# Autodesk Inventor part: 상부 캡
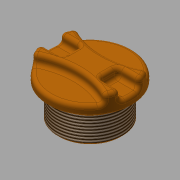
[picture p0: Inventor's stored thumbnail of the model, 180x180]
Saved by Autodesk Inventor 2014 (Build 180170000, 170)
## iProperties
Created: 2016-09
Part Number: 상부 캡
Material: ABS 플라스틱
Document SubType Name: Modeling
Designer: mduedu
Density: 1.06 g/cm^3
Appearance: 주황색
Mass: 22.8245 g
Surface Area: 69.6423 cm^2
Volume: 21.5325 cm^3
Author: mduedu
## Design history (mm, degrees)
sketch "스케치1"
  geometry: C1 r 22.5 at (0, 0); 1 further point
  constraints: 1 centre point, 1 coincident
  dimensions: "d0" = 45 diameter of C1
extrude "돌출1" new body sketch "스케치1" distance "d1" = 10; taper "d2" = 0 deg
sketch "스케치2" dims "d4" = 80
  geometry: C1 r 22.5 at (0, 0) reference; 3 further points
  constraints: 3 vertical alignment, 2 other
  dimensions: "d3" = 7 distance of point (0, 7) point (0, 0)
extrude "돌출2" cut sketch "스케치2" distance "d5" = 5; taper "d6" = 0 deg
sketch "스케치3"
  geometry: L1 (-22.5, 0)-(0, 0); L2 (-21.937, 5)-(-10, 5); L3 (-10, 5)-(-10, -5); L4 (-10, -5)-(-21.937, -5); A1 r 22.5 centre (0, 0) between (-19.118, 11.864) and (-19.118, -11.864) reference; A2 r 22.5 centre (0, 0) between (-21.937, 5) and (-21.937, -5); 1 further point
  constraints: 8 end point, 5 point on circle, 2 horizontal, 1 centre point, 1 coincident, 1 parallel, 1 perpendicular, 1 symmetric about line
  dimensions: "d7" = 10 distance from line of L3 point (0, 0); "d8" = 10 distance of L2.end L3.end
extrude "돌출3" cut sketch "스케치3" distance "d9" = 5; taper "d10" = 0 deg
fillet "모깎기1" dims "d11" = 2
fillet "모깎기2" dims "d12" = 2
fillet "모깎기3" dims "d13" = 2
sketch "스케치4"
  geometry: C1 r 17.5 at (0, 0); 1 further point
  constraints: 1 centre point, 1 coincident
  dimensions: "d14" = 35 diameter of C1
extrude "돌출4" join sketch "스케치4" distance "d15" = 17; taper "d16" = 0 deg
sketch "스케치5"
  geometry: C1 r 12.5 at (0, 0); 1 further point
  constraints: 1 centre point, 1 coincident
  dimensions: "d17" = 25 diameter of C1
extrude "돌출5" cut sketch "스케치5" distance "d18" = 10; taper "d19" = 0 deg
fillet "모깎기4" dims "d20" = 3
sketch "스케치6"
  geometry: L1 (7, 7)-(8, 7) reference; L2 (10, 5)-(10, -5) reference; L3 (8, -7)-(7, -7) reference; L4 (5, -9)-(5, -20.5) reference; L5 (3, -22.5)-(0, -22.5) reference; L6 (0, -22.5)-(0, -17.5) reference; L7 (0, -17.5)-(-17, -17.5) reference; L8 (-17, -17.5)-(-17, -12.5) reference; L9 (-17, -12.5)-(-10, -12.5) reference; L10 (-7, -9.5)-(-7, 9.5) reference; L11 (-10, 12.5)-(-17, 12.5) reference; L12 (-17, 12.5)-(-17, 17.5) reference; L13 (-17, 17.5)-(0, 17.5) reference; L14 (0, 17.5)-(0, 22.5) reference; L15 (0, 22.5)-(3, 22.5) reference; L16 (5, 20.5)-(5, 9) reference; L17 (0, -17.5)-(-2, -17.5); L18 (-2, -17.5)-(-2, -16.5); L19 (-2, -16.5)-(0, -16.5); L20 (0, -16.5)-(0, -17.5); L21 (0, 0)-(-7, 0); A1 r 2 centre (7, 9) between (5, 9) and (7, 7) reference; A2 r 2 centre (8, 5) between (10, 5) and (8, 7) reference; A3 r 2 centre (8, -5) between (8, -7) and (10, -5) reference; A4 r 2 centre (7, -9) between (7, -7) and (5, -9) reference; A5 r 2 centre (3, -20.5) between (3, -22.5) and (5, -20.5) reference; A6 r 3 centre (-10, -9.5) between (-10, -12.5) and (-7, -9.5) reference; A7 r 3 centre (-10, 9.5) between (-7, 9.5) and (-10, 12.5) reference; A8 r 2 centre (3, 20.5) between (5, 20.5) and (3, 22.5) reference
  constraints: 10 end point, 2 parallel, 1 horizontal, 1 midpoint, 1 perpendicular
  dimensions: "d26" = 2 distance of L6.end L17.end; "d27" = 1 distance of L17.end L18.end
revolve "회전1" sketch "스케치6" stored, may be unused: angle "d28" = 90 deg
feature "스레드1" dims "d21" = 10, "d22" = 0
chamfer "모따기1" distance "d23" = 1; stored, may be unused: second distance "d24" = 2, angle "d25" = 45 deg
sketch "스케치7"
  geometry: L1 (7, 7)-(8, 7) reference; L2 (10, 5)-(10, -5) reference; L3 (8, -7)-(7, -7) reference; L4 (5, -9)-(5, -20.5) reference; L5 (3, -22.5)-(0, -22.5) reference; L6 (0, -22.5)-(0, -16.5) reference; L7 (0, -16.5)-(-2, -16.5) reference; L8 (-2, -16.5)-(-3, -17.5) reference; L9 (-3, -17.5)-(-16, -17.5) reference; L10 (-16, -17.5)-(-17, -16.5) reference; L11 (-17, -16.5)-(-17, -12.5) reference; L12 (-17, -12.5)-(-10, -12.5) reference; L13 (-7, -9.5)-(-7, 9.5) reference; L14 (-10, 12.5)-(-17, 12.5) reference; L15 (-17, 12.5)-(-17, 16.5) reference; L16 (-17, 16.5)-(-16, 17.5) reference; L17 (-16, 17.5)-(-3, 17.5) reference; L18 (-3, 17.5)-(-2, 16.5) reference; L19 (-2, 16.5)-(0, 16.5) reference; L20 (0, 16.5)-(0, 22.5) reference; L21 (0, 22.5)-(3, 22.5) reference; L22 (5, 20.5)-(5, 9) reference; L23 (0, -22.5)-(1, -22.5); L24 (1, -22.5)-(1, -21.5); L25 (1, -21.5)-(0, -21.5); L26 (0, -21.5)-(0, -22.5); L27 (0, 0)-(-7, 0); A1 r 2 centre (7, 9) between (5, 9) and (7, 7) reference; A2 r 2 centre (8, 5) between (10, 5) and (8, 7) reference; A3 r 2 centre (8, -5) between (8, -7) and (10, -5) reference; A4 r 2 centre (7, -9) between (7, -7) and (5, -9) reference; A5 r 2 centre (3, -20.5) between (3, -22.5) and (5, -20.5) reference; A6 r 3 centre (-10, -9.5) between (-10, -12.5) and (-7, -9.5) reference; A7 r 3 centre (-10, 9.5) between (-7, 9.5) and (-10, 12.5) reference; A8 r 2 centre (3, 20.5) between (5, 20.5) and (3, 22.5) reference
  constraints: 10 end point, 2 parallel, 1 horizontal, 1 midpoint, 1 perpendicular
  dimensions: "d29" = 1 distance of L25.end L24.end; "d30" = 1 distance of L24.end L23.end
revolve "회전2" sketch "스케치7" stored, may be unused: angle "d31" = 90 deg
node "솔리드1"
mirror "대칭1"
mirror "대칭2"
node "투영된 루프1"
node "절단 모서리 투영1"
node "절단 모서리 투영2"
